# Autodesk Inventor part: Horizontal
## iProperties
Created: 2008-04
Part Number: Horizontal
Document SubType Name: Modeling
Designer: Jayson Martinez
Density: 1 g/cm^3
Author: Jayson Martinez
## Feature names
1. Extrusion1
